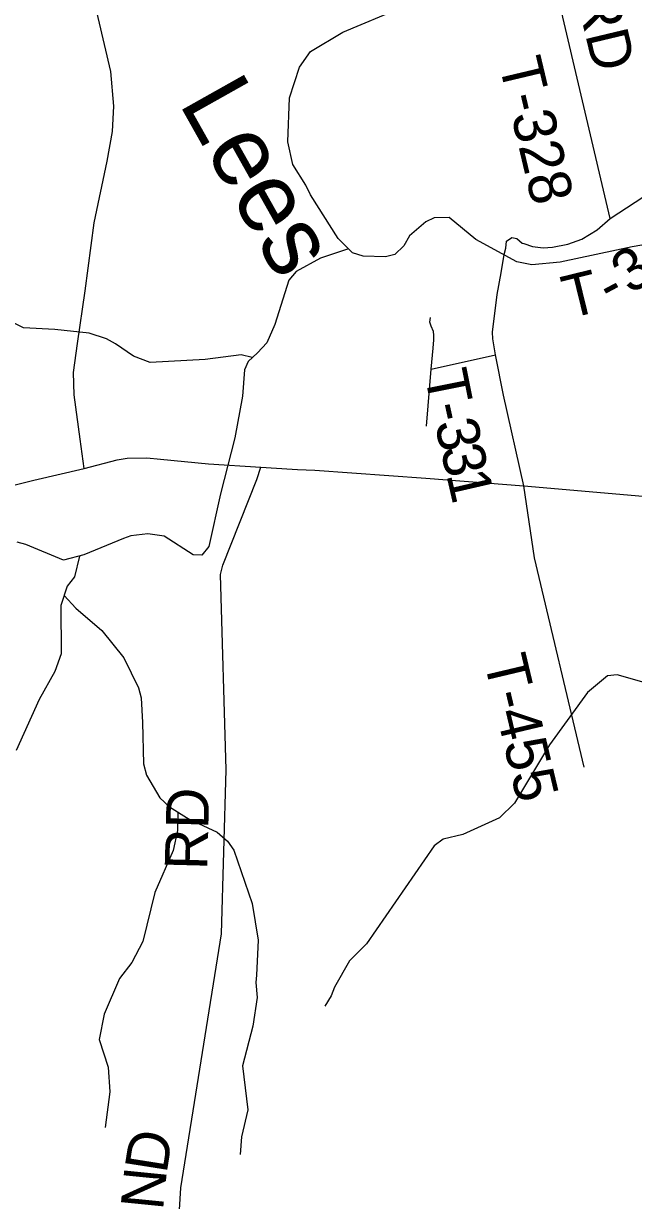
# Model space of a CAD drawing. Extents: x 1525783 to 1900577, y 218250 to 627376.
# Drawn here: x 1660383 to 1664681, y 487300 to 495597 of the extents above; entities that cross this region are included whole.
import ezdxf

# ---------------------------------------------------------------- set-up
doc = ezdxf.new("R2010")
doc.units = 0
for name, color, linetype in [('GM_X_County_Road', 7, 'Continuous'), ('GM_X_County_Road_Text', 7, 'Continuous'), ('GM_X_Minor_River', 7, 'Continuous'), ('GM_X_Minor_River_Text', 7, 'Continuous'), ('GM_X_State_Route', 7, 'Continuous'), ('GM_X_Township_Road', 7, 'Continuous'), ('GM_X_Township_Road_Text', 7, 'Continuous'), ('GM_X_Township_Subdivision', 7, 'Continuous')]:
    doc.layers.add(name, color=color, linetype=linetype)

msp = doc.modelspace()

# ---------------------------------------------------------------- linework, layer by layer
at = {"layer": 'GM_X_County_Road'}
msp.add_lwpolyline([(1661298.6, 484163.9), (1661314.7, 484283.7), (1661441.1, 486576.4), (1661492.3, 487388.7), (1661778.5, 489178.7), (1661811.7, 490336.2), (1661770.4, 491712.5), (1661786.5, 491779.3), (1662027.5, 492382.1), (1662054.7, 492470.4)], dxfattribs=at)
at = {"layer": 'GM_X_Minor_River'}
for points in [[(1665162.5, 494107.1), (1664671.1, 494022.4), (1664165.2, 493913.8), (1663964, 493896.8), (1663859.9, 493916.5), (1663571.1, 494075.3), (1663382.7, 494228.7), (1663276.2, 494226.3), (1663217.5, 494199.1), (1663101.5, 494100.6), (1663062.2, 494029), (1662999, 493967.8), (1662934.5, 493952.7), (1662775.8, 493957.1), (1662699.9, 493980.4), (1662601, 494082.2), (1662405, 494388.1), (1662371.9, 494456.8), (1662279.8, 494602.7), (1662244.1, 494763.8), (1662257, 495072.5), (1662326.7, 495290.1), (1662404.7, 495399.2), (1662631.8, 495536.2), (1663048.3, 495710.4)], [(1662672.2, 494008.9), (1662474.3, 493943.7), (1662304.1, 493848), (1662253, 493788.6), (1662153.7, 493475.2), (1662097.4, 493345.6), (1662032, 493276.4), (1661964.8, 493215.3), (1661939.7, 493155.5), (1661924.8, 492969.1), (1661872, 492675), (1661771.4, 492281.3), (1661689.3, 491909.5), (1661640.1, 491848), (1661577.9, 491851), (1661373, 491982.5), (1661258.8, 492000.3), (1661138.1, 491986.1), (1661087.5, 491966.8), (1660806.5, 491850.8), (1660665.3, 491812.8), (1660397.9, 491925.3), (1660337.9, 491940.2)], [(1661994.8, 493242.6), (1661915.3, 493262.2), (1661661.7, 493227.9), (1661275.7, 493207.8), (1661157.9, 493251.7), (1661030.7, 493337.9), (1660967, 493375), (1660845, 493413), (1660604.4, 493440.8), (1660383.6, 493452.2), (1660176.3, 493551.7), (1660064, 493561.4), (1659630.6, 493465.8), (1659502, 493463.7), (1659208.6, 493584.6), (1659086.4, 493600.5), (1659032.1, 493599.4), (1658901.2, 493579.3), (1658745.5, 493509.5), (1658486.7, 493276.7), (1658349.3, 493094.3), (1658326.4, 493042.5)], [(1660777.2, 491842.9), (1660741.8, 491695.3), (1660690.6, 491629.9), (1660646.3, 491494.1), (1660647, 491153.1), (1660602.8, 491029.4), (1660493.3, 490832.5), (1660331, 490471.8)], [(1660669.3, 491564.6), (1660750.4, 491474.5), (1660934.8, 491317.2), (1661088.5, 491126.3), (1661193.6, 490914), (1661212.6, 490843.5), (1661221.9, 490668.8), (1661227.4, 490377.8), (1661250.3, 490297.2), (1661342.2, 490137.3), (1661411.5, 490074.1), (1661550.7, 489987.7), (1661748.2, 489896.4), (1661819.5, 489833.1), (1661864.7, 489768.2), (1661993.4, 489393.1), (1662035.6, 489135.7), (1662023.7, 488889.1), (1662018.9, 488837), (1662029.3, 488730.5), (1661998, 488528.4), (1661925.3, 488248.6), (1661962.7, 487939.1), (1661919.5, 487747.2), (1661909.5, 487623)], [(1665031.7, 491074.8), (1664868.5, 490978), (1664739.6, 490955.9), (1664565.6, 491004.7), (1664497.2, 490997.8), (1664356.8, 490881.5), (1664089.9, 490512.5), (1663842.4, 490101), (1663736.3, 489996.3), (1663477.4, 489879.9), (1663340.3, 489845.9), (1663277.3, 489798.7), (1662800.5, 489107.9), (1662680.1, 488989.4), (1662574.8, 488804.4), (1662549.7, 488742.6), (1662506.4, 488669)], [(1661469.1, 490038.4), (1661467.1, 489906.7), (1661436.8, 489766.8), (1661307.7, 489471.8), (1661223.9, 489126), (1661145.3, 488976.8), (1661059.1, 488863.8), (1660950.8, 488612.6), (1660915.8, 488434.6), (1660979.1, 488239.1), (1660990.4, 488064.4), (1660958.4, 487814.1)]]:
    msp.add_lwpolyline(points, dxfattribs=at)
at = {"layer": 'GM_X_State_Route'}
for points in [[(1660810.7, 492460.8), (1660782.6, 492666.5), (1660739.4, 492978.7), (1660735.3, 493137.6), (1660763.8, 493341.3), (1660816.8, 493712), (1660881.5, 494191.3), (1660972.8, 494627.6), (1661010.2, 494835.8), (1661019, 495014.3), (1660998.6, 495257.6), (1660785.3, 496172.5), (1660389.7, 497660.4), (1660267.7, 498365), (1660221.2, 498478.2), (1660146.4, 498587.8), (1659818.9, 499008.5), (1659694.6, 499173.1), (1659612.4, 499323), (1659559.9, 499572.8), (1659296.4, 502574.6), (1659279.6, 502970.6), (1659301.8, 503400.6)], [(1660810.7, 492460.8), (1661043.5, 492520.8), (1661114.1, 492533), (1661251.4, 492534.3), (1661347.4, 492525.3)], [(1661347.4, 492525.3), (1661685, 492493.6), (1662054.7, 492470.4), (1662274.9, 492455.5), (1662312.3, 492453.6)], [(1658680, 491714.1), (1658703.6, 491722.5), (1658788.4, 491763.3), (1659125, 491937.3), (1659279.4, 492023.7), (1659386, 492088), (1659466.9, 492119.3), (1659606.6, 492159.7), (1659894.5, 492237.7), (1660455.7, 492378.8), (1660810.7, 492460.8)], [(1662312.3, 492453.6), (1662435.1, 492447.2), (1663217.7, 492390.6), (1663908.7, 492338), (1664908, 492251.4), (1665337.1, 492220.7), (1665458.7, 492211.8), (1665669.3, 492188.3), (1665705.4, 492185.4)]]:
    msp.add_lwpolyline(points, dxfattribs=at)
at = {"layer": 'GM_X_Township_Road'}
for points in [[(1664516.7, 494223), (1663783.8, 497342.4), (1663707.7, 497377), (1663664.2, 497491.7), (1663208.1, 499802.2), (1663150.1, 500165.8), (1663074.5, 500615.8), (1662430.1, 501390.4), (1661328.8, 502673.8), (1660751.9, 503299.6), (1660683.2, 503380.5), (1660600.6, 503477.7), (1660532.4, 503557.9), (1660860, 503978.6)], [(1663907.8, 494045.3), (1663969.5, 494023.9), (1664044.1, 494015.7), (1664110.5, 494021.2), (1664218.2, 494040.5), (1664317.7, 494076.5), (1664425.5, 494142.8), (1664516.7, 494223), (1664808.8, 494412.2), (1665578.9, 494814.6), (1665976.2, 495040.8), (1666242.4, 495195.6), (1666417.7, 495276.7), (1666646.9, 495293.3), (1668417.7, 495362.2), (1669021.3, 495143.6), (1669363.9, 495027.6)], [(1663747.6, 493839.2), (1663770.5, 493968.7), (1663781.5, 494012.9), (1663787.1, 494062.7), (1663823, 494087.5), (1663858.9, 494082), (1663897.6, 494048.8), (1663907.8, 494045.3)], [(1663908.7, 492338), (1663765.1, 492976.3), (1663707.7, 493261.3), (1663690.3, 493374.5), (1663687.6, 493421.5), (1663720.8, 493686.8), (1663747.6, 493839.2)], [(1664333.8, 490354), (1663984.4, 491831.1), (1663908.7, 492338)]]:
    msp.add_lwpolyline(points, dxfattribs=at)
at = {"layer": 'GM_X_Township_Subdivision'}
for points in [[(1663254.1, 493161.1), (1663270.2, 493308.1), (1663275.2, 493366), (1663275.2, 493400.4), (1663272.6, 493426.9), (1663255.4, 493463.9), (1663244.8, 493491.7), (1663251.4, 493523.4)], [(1663254.1, 493161.1), (1663707.7, 493261.3)], [(1663223.2, 492757.3), (1663254.1, 493161.1)]]:
    msp.add_lwpolyline(points, dxfattribs=at)

# ---------------------------------------------------------------- texts
at = {"layer": 'GM_X_County_Road_Text'}
for s, rotation, p in [('RD', 88.51842, (1661677.1, 489626.8)), ('D', 81.04072, (1661390.6, 487483.5)), ('N', 84.28795, (1661364.9, 487225.3))]:
    msp.add_text(s, height=300, rotation=rotation, dxfattribs=at).set_placement(p)
at = {"layer": 'GM_X_Minor_River_Text'}
msp.add_text('Lees', height=499.98, rotation=299.33728, dxfattribs=at).set_placement((1661473.7, 495037.8))
at = {"layer": 'GM_X_Township_Road_Text'}
for s, rotation, p in [('RD', 283.43808, (1664272.7, 495802.4)), ('T-328', 283.3535, (1663730.5, 495320.3)), ('3', 36.17848, (1664665.6, 493680.1)), ('T', 13.77743, (1664223.7, 493515.2)), ('-', 28.01263, (1664517.4, 493597.5)), ('T', 281.29733, (1663206.8, 493128.2)), ('-', 282.32889, (1663251.9, 492902.4)), ('3', 282.65759, (1663278.6, 492780.2)), ('3', 282.92689, (1663319.5, 492598.4)), ('1', 282.98627, (1663360.9, 492418)), ('T-455', 283.3535, (1663624.9, 491109.5))]:
    msp.add_text(s, height=300, rotation=rotation, dxfattribs=at).set_placement(p)

doc.saveas('drawing.dxf')
